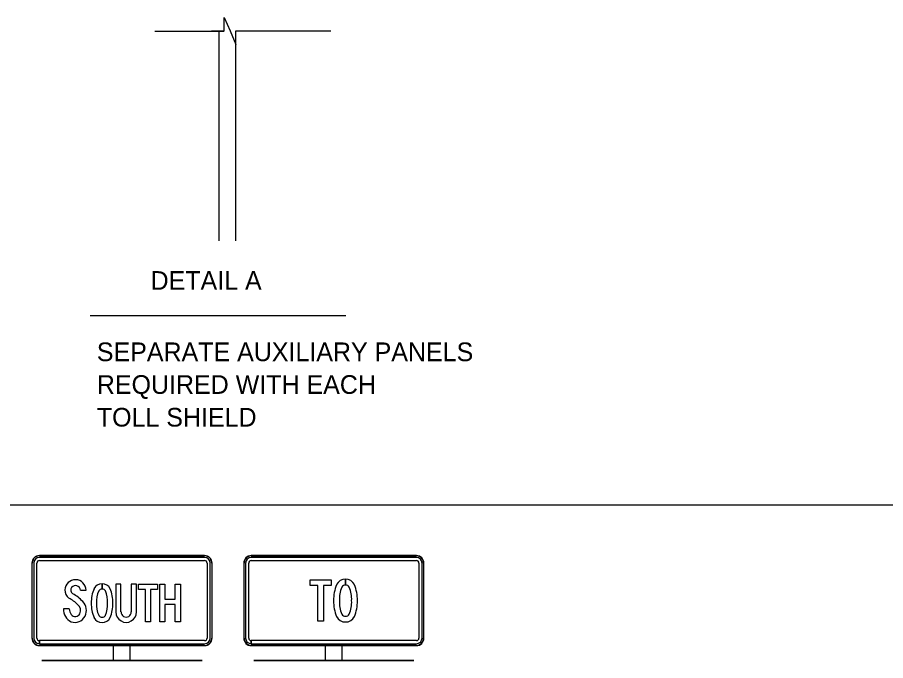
# Model space of a CAD drawing. Extents: x 530729 to 531367, y 1533250 to 1533664.
# Drawn here: x 530888.6 to 531018.7, y 1533454.4 to 1533550.8 of the extents above; entities that cross this region are included whole.
import ezdxf

# ---------------------------------------------------------------- set-up
doc = ezdxf.new("R2010")
doc.units = 0
for name, color, linetype in [('SheetBorder_dp', 7, 'Continuous'), ('SignPanel', 7, 'Continuous'), ('SignSupport', 7, 'Continuous'), ('TextLabel', 7, 'Continuous')]:
    doc.layers.add(name, color=color, linetype=linetype)

msp = doc.modelspace()

# ---------------------------------------------------------------- linework, layer by layer
at = {"layer": 'SheetBorder_dp'}
msp.add_line((530751.46, 1533477.75), (531367.46, 1533477.75), dxfattribs=at)
at = {"layer": 'SignPanel'}
for p, q in [((530918.87, 1533517.32), (530918.88, 1533548.76)), ((530921.38, 1533517.32), (530921.39, 1533548.78)), ((530916.69, 1533470.18), (530891.94, 1533470.18)), ((530916.69, 1533470.18), (530891.94, 1533470.18)), ((530891.94, 1533470.13), (530916.69, 1533470.13)), ((530916.69, 1533469.9), (530891.94, 1533469.9)), ((530891.94, 1533469.43), (530916.69, 1533469.43)), ((530903.06, 1533470.18), (530905.57, 1533470.18)), ((530948.43, 1533470.18), (530923.68, 1533470.18)), ((530948.43, 1533470.18), (530923.68, 1533470.18)), ((530923.68, 1533470.13), (530948.43, 1533470.13)), ((530948.43, 1533469.9), (530923.68, 1533469.9)), ((530923.68, 1533469.43), (530948.43, 1533469.43)), ((530934.8, 1533470.18), (530937.31, 1533470.18)), ((530890.81, 1533469.05), (530890.81, 1533457.8)), ((530890.81, 1533469.05), (530890.81, 1533457.8)), ((530890.86, 1533457.8), (530890.86, 1533469.05)), ((530891.09, 1533469.05), (530891.09, 1533457.8)), ((530891.56, 1533457.8), (530891.56, 1533469.05)), ((530917.06, 1533469.05), (530917.06, 1533457.8)), ((530917.53, 1533457.8), (530917.53, 1533469.05)), ((530917.77, 1533469.05), (530917.77, 1533457.8)), ((530917.81, 1533457.8), (530917.81, 1533469.05)), ((530917.81, 1533457.8), (530917.81, 1533469.05)), ((530922.56, 1533469.05), (530922.56, 1533457.8)), ((530922.56, 1533469.05), (530922.56, 1533457.8)), ((530922.6, 1533457.8), (530922.6, 1533469.05)), ((530922.84, 1533469.05), (530922.84, 1533457.8)), ((530923.31, 1533457.8), (530923.31, 1533469.05)), ((530948.81, 1533469.05), (530948.81, 1533457.8)), ((530949.28, 1533457.8), (530949.28, 1533469.05)), ((530949.51, 1533469.05), (530949.51, 1533457.8)), ((530949.56, 1533457.8), (530949.56, 1533469.05)), ((530949.56, 1533457.8), (530949.56, 1533469.05)), ((530901.34, 1533465.14), (530901.34, 1533465.93)), ((530901.34, 1533465.93), (530901.34, 1533465.14)), ((530901.34, 1533465.14), (530901.34, 1533465.93)), ((530901.34, 1533465.93), (530901.34, 1533465.14)), ((530903.4, 1533465.87), (530903.4, 1533461.72)), ((530903.4, 1533465.87), (530903.4, 1533461.72)), ((530903.4, 1533465.87), (530903.4, 1533461.72)), ((530937.81, 1533465.74), (530937.81, 1533466.62)), ((530937.81, 1533466.62), (530937.81, 1533465.74)), ((530937.81, 1533465.74), (530937.81, 1533466.62)), ((530937.81, 1533466.62), (530937.81, 1533465.74)), ((530898.09, 1533464.97), (530898.94, 1533464.97)), ((530898.09, 1533464.97), (530898.94, 1533464.97)), ((530898.09, 1533464.97), (530898.94, 1533464.97)), ((530896.43, 1533462.19), (530895.56, 1533462.19)), ((530896.43, 1533462.19), (530895.56, 1533462.19)), ((530896.43, 1533462.19), (530895.56, 1533462.19)), ((530891.94, 1533456.96), (530891.94, 1533457.43)), ((530916.69, 1533457.43), (530891.94, 1533457.43)), ((530891.94, 1533457.43), (530891.94, 1533456.96)), ((530891.94, 1533456.96), (530916.69, 1533456.96)), ((530891.94, 1533456.68), (530891.94, 1533456.73)), ((530916.69, 1533456.73), (530891.94, 1533456.73)), ((530891.94, 1533456.73), (530891.94, 1533456.68)), ((530891.94, 1533456.68), (530916.69, 1533456.68)), ((530891.94, 1533456.68), (530916.69, 1533456.68)), ((530903.05, 1533454.43), (530903.05, 1533456.73)), ((530905.56, 1533454.43), (530905.56, 1533456.73)), ((530923.68, 1533456.96), (530923.68, 1533457.43)), ((530923.68, 1533456.68), (530923.68, 1533456.73)), ((530948.43, 1533456.73), (530923.68, 1533456.73)), ((530923.68, 1533456.73), (530923.68, 1533456.68)), ((530923.68, 1533456.68), (530948.43, 1533456.68)), ((530923.68, 1533456.68), (530948.43, 1533456.68)), ((530948.43, 1533457.43), (530923.69, 1533457.43)), ((530923.69, 1533457.43), (530923.69, 1533456.96)), ((530923.69, 1533456.96), (530948.43, 1533456.96)), ((530934.8, 1533454.43), (530934.8, 1533456.68)), ((530937.31, 1533454.43), (530937.31, 1533456.68))]:
    msp.add_line(p, q, dxfattribs=at)
for points in [[(530904.17, 1533461.72), (530904.17, 1533465.87), (530903.4, 1533465.87)], [(530904.17, 1533461.72), (530904.17, 1533465.87), (530903.4, 1533465.87)], [(530904.17, 1533461.72), (530904.17, 1533465.87), (530903.4, 1533465.87)], [(530906.47, 1533461.72), (530906.47, 1533465.87), (530905.7, 1533465.87), (530905.7, 1533461.72)], [(530906.47, 1533461.72), (530906.47, 1533465.87), (530905.7, 1533465.87), (530905.7, 1533461.72)], [(530906.47, 1533461.72), (530906.47, 1533465.87), (530905.7, 1533465.87), (530905.7, 1533461.72)], [(530916.31, 1533454.43), (530892.31, 1533454.43)], [(530892.31, 1533454.43), (530916.31, 1533454.43)], [(530948.06, 1533454.43), (530924.06, 1533454.43)], [(530924.06, 1533454.43), (530948.06, 1533454.43)]]:
    msp.add_lwpolyline(points, dxfattribs=at)
for points in [[(530907.84, 1533465.08), (530906.81, 1533465.08), (530906.81, 1533465.87), (530909.64, 1533465.87), (530909.64, 1533465.08), (530908.61, 1533465.08), (530908.61, 1533460.24), (530907.84, 1533460.24)], [(530907.84, 1533465.08), (530906.81, 1533465.08), (530906.81, 1533465.87), (530909.64, 1533465.87), (530909.64, 1533465.08), (530908.61, 1533465.08), (530908.61, 1533460.24), (530907.84, 1533460.24)], [(530907.84, 1533465.08), (530906.81, 1533465.08), (530906.81, 1533465.87), (530909.64, 1533465.87), (530909.64, 1533465.08), (530908.61, 1533465.08), (530908.61, 1533460.24), (530907.84, 1533460.24)], [(530909.98, 1533465.87), (530910.76, 1533465.87), (530910.76, 1533463.62), (530912.28, 1533463.62), (530912.28, 1533465.87), (530913.06, 1533465.87), (530913.06, 1533460.24), (530912.28, 1533460.24), (530912.28, 1533462.83), (530910.76, 1533462.83), (530910.76, 1533460.24), (530909.98, 1533460.24)], [(530909.98, 1533465.87), (530910.76, 1533465.87), (530910.76, 1533463.62), (530912.28, 1533463.62), (530912.28, 1533465.87), (530913.06, 1533465.87), (530913.06, 1533460.24), (530912.28, 1533460.24), (530912.28, 1533462.83), (530910.76, 1533462.83), (530910.76, 1533460.24), (530909.98, 1533460.24)], [(530909.98, 1533465.87), (530910.76, 1533465.87), (530910.76, 1533463.62), (530912.28, 1533463.62), (530912.28, 1533465.87), (530913.06, 1533465.87), (530913.06, 1533460.24), (530912.28, 1533460.24), (530912.28, 1533462.83), (530910.76, 1533462.83), (530910.76, 1533460.24), (530909.98, 1533460.24)], [(530933.65, 1533465.67), (530932.52, 1533465.67), (530932.52, 1533466.54), (530935.64, 1533466.54), (530935.64, 1533465.67), (530934.51, 1533465.67), (530934.51, 1533460.32), (530933.65, 1533460.32)], [(530933.65, 1533465.67), (530932.52, 1533465.67), (530932.52, 1533466.54), (530935.64, 1533466.54), (530935.64, 1533465.67), (530934.51, 1533465.67), (530934.51, 1533460.32), (530933.65, 1533460.32)], [(530933.65, 1533465.67), (530932.52, 1533465.67), (530932.52, 1533466.54), (530935.64, 1533466.54), (530935.64, 1533465.67), (530934.51, 1533465.67), (530934.51, 1533460.32), (530933.65, 1533460.32)]]:
    msp.add_lwpolyline(points, close=True, dxfattribs=at)
for centre, radius, start, end in [((530891.94, 1533469.05), 1.12, 90, 180), ((530891.94, 1533469.05), 1.12, 90, 180), ((530891.94, 1533469.05), 1.08, 90, 180), ((530891.94, 1533469.05), 0.844, 90, 180), ((530891.94, 1533469.05), 0.375, 90, 180), ((530916.69, 1533469.05), 1.12, 0, 90), ((530916.69, 1533469.05), 1.12, 0, 90), ((530916.69, 1533469.05), 1.08, 0, 90), ((530916.69, 1533469.05), 0.844, 0, 90), ((530916.69, 1533469.05), 0.375, 0, 90), ((530923.68, 1533469.05), 1.12, 90, 180), ((530923.68, 1533469.05), 1.12, 90, 180), ((530923.68, 1533469.05), 1.08, 90, 180), ((530923.68, 1533469.05), 0.844, 90, 180), ((530923.68, 1533469.05), 0.375, 90, 180), ((530948.43, 1533469.05), 1.12, 0, 90), ((530948.43, 1533469.05), 1.12, 0, 90), ((530948.43, 1533469.05), 1.08, 0, 90), ((530948.43, 1533469.05), 0.844, 0, 90), ((530948.43, 1533469.05), 0.375, 0, 90), ((530891.94, 1533457.8), 1.12, 180, 270), ((530891.94, 1533457.8), 1.12, 180, 270), ((530891.94, 1533457.8), 1.08, 180, 270), ((530891.94, 1533457.8), 0.844, 180, 270), ((530891.94, 1533457.8), 0.375, 180, 270), ((530916.69, 1533457.8), 1.12, 270, 0), ((530916.69, 1533457.8), 0.844, 270, 0), ((530916.69, 1533457.8), 0.375, 270, 0), ((530916.69, 1533457.8), 1.12, 270, 0), ((530916.69, 1533457.8), 1.08, 270, 0), ((530923.68, 1533457.8), 1.12, 180, 270), ((530923.68, 1533457.8), 1.12, 180, 270), ((530923.68, 1533457.8), 1.08, 180, 270), ((530923.68, 1533457.8), 0.844, 180, 270), ((530923.68, 1533457.8), 0.375, 180, 270), ((530948.43, 1533457.8), 1.12, 270, 0), ((530948.43, 1533457.8), 0.844, 270, 0), ((530948.43, 1533457.8), 0.375, 270, 0), ((530948.43, 1533457.8), 1.12, 270, 0), ((530948.43, 1533457.8), 1.08, 270, 0)]:
    msp.add_arc(centre, radius, start, end, dxfattribs=at)
for centre, major_axis, start_param, end_param in [((530897.35, 1533464.93), (0, 1.62), 4.736267, 7.790596), ((530897.35, 1533464.93), (0, 1.62), 4.736267, 7.790596), ((530897.35, 1533464.93), (0, 1.62), 4.736267, 7.790596), ((530897.25, 1533465.01), (0, 0.626), 0.87378, 2.656959), ((530897.25, 1533465.01), (0, 0.626), 0.87378, 2.656959), ((530897.25, 1533465.01), (0, 0.626), 0.87378, 2.656959), ((530897.34, 1533464.91), (0, 0.76), 4.786904, 7.140738), ((530897.34, 1533464.91), (0, 0.76), 4.786904, 7.140738), ((530897.34, 1533464.91), (0, 0.76), 4.786904, 7.140738), ((530901.29, 1533464.61), (0, 1.33), 6.248265, 7.383959), ((530901.29, 1533464.61), (0, 1.33), 6.248265, 7.383959), ((530901.29, 1533464.61), (0, 1.33), 6.248265, 7.383959), ((530901.38, 1533464.61), (0, 1.33), 5.182411, 6.318105), ((530901.38, 1533464.61), (0, 1.33), 5.182411, 6.317893), ((530901.38, 1533464.61), (0, 1.33), 5.182411, 6.317893), ((530941.83, 1533463.53), (0, 5.9), 1.174158, 1.59042), ((530941.83, 1533463.53), (0, 5.9), 1.174158, 1.59042), ((530941.83, 1533463.53), (0, 5.9), 1.174158, 1.59042), ((530937.76, 1533465.15), (0, 1.47), 6.248265, 7.383959), ((530937.76, 1533465.15), (0, 1.47), 6.248265, 7.383959), ((530937.76, 1533465.15), (0, 1.47), 6.248265, 7.383959), ((530941.45, 1533463.63), (0, 4.64), 1.169623, 1.616135), ((530941.45, 1533463.63), (0, 4.64), 1.169623, 1.616135), ((530941.45, 1533463.63), (0, 4.64), 1.169623, 1.616135), ((530937.77, 1533465.11), (0, 0.627), 6.22959, 7.30809), ((530937.77, 1533465.11), (0, 0.627), 6.22959, 7.30809), ((530937.77, 1533465.11), (0, 0.627), 6.22959, 7.30809), ((530937.86, 1533465.15), (0, 1.47), 5.182411, 6.318105), ((530937.86, 1533465.15), (0, 1.47), 5.182411, 6.317893), ((530937.86, 1533465.15), (0, 1.47), 5.182411, 6.317893), ((530937.84, 1533465.11), (0, 0.627), 5.258281, 6.33678), ((530937.84, 1533465.11), (0, 0.627), 5.258281, 6.336283), ((530937.84, 1533465.11), (0, 0.627), 5.258281, 6.336283), ((530934.16, 1533463.63), (0, 4.64), 4.667051, 5.113562), ((530934.16, 1533463.63), (0, 4.64), 4.667051, 5.113562), ((530934.16, 1533463.63), (0, 4.64), 4.667051, 5.113562), ((530933.78, 1533463.53), (0, 5.9), 4.692766, 5.109028), ((530933.78, 1533463.53), (0, 5.9), 4.692766, 5.109028), ((530933.78, 1533463.53), (0, 5.9), 4.692766, 5.109028), ((530897.19, 1533464.98), (0, 1.45), 1.534831, 2.511766), ((530897.19, 1533464.98), (0, 1.45), 1.534831, 2.511766), ((530897.19, 1533464.98), (0, 1.45), 1.534831, 2.511766), ((530894.13, 1533459.21), (0, 5.97), 5.462886, 5.782242), ((530894.13, 1533459.21), (0, 5.97), 5.462886, 5.782242), ((530894.13, 1533459.21), (0, 5.97), 5.462886, 5.782242), ((530904.97, 1533463.15), (0, 5.33), 1.174158, 1.59042), ((530904.97, 1533463.15), (0, 5.33), 1.174158, 1.59042), ((530904.97, 1533463.15), (0, 5.33), 1.174158, 1.59042), ((530904.63, 1533463.23), (0, 4.19), 1.169623, 1.616135), ((530904.63, 1533463.23), (0, 4.19), 1.169623, 1.616135), ((530904.63, 1533463.23), (0, 4.19), 1.169623, 1.616135), ((530901.31, 1533464.58), (0, 0.567), 6.22959, 7.30809), ((530901.31, 1533464.58), (0, 0.567), 6.22959, 7.30809), ((530901.31, 1533464.58), (0, 0.567), 6.22959, 7.30809), ((530901.37, 1533464.58), (0, 0.567), 5.258281, 6.33678), ((530901.37, 1533464.58), (0, 0.567), 5.258281, 6.336283), ((530901.37, 1533464.58), (0, 0.567), 5.258281, 6.336283), ((530898.04, 1533463.23), (0, 4.19), 4.667051, 5.113562), ((530898.04, 1533463.23), (0, 4.19), 4.667051, 5.113562), ((530898.04, 1533463.23), (0, 4.19), 4.667051, 5.113562), ((530897.7, 1533463.15), (0, 5.33), 4.692766, 5.109028), ((530897.7, 1533463.15), (0, 5.33), 4.692766, 5.109028), ((530897.7, 1533463.15), (0, 5.33), 4.692766, 5.109028), ((530893.39, 1533458.26), (0, 6.31), 5.515137, 5.786988), ((530893.39, 1533458.26), (0, 6.31), 5.515137, 5.786988), ((530893.39, 1533458.26), (0, 6.31), 5.515137, 5.786988), ((530897.06, 1533461.94), (0, 1.08), 4.254409, 5.632398), ((530897.06, 1533461.94), (0, 1.08), 4.254409, 5.632398), ((530897.06, 1533461.94), (0, 1.08), 4.254409, 5.632398), ((530897.08, 1533461.94), (0, 1.93), 4.260987, 5.485755), ((530897.08, 1533461.94), (0, 1.93), 4.260987, 5.485755), ((530897.08, 1533461.94), (0, 1.93), 4.260987, 5.485755), ((530904.97, 1533462.94), (0, 5.33), 1.551173, 1.967435), ((530904.97, 1533462.94), (0, 5.33), 1.551173, 1.967435), ((530904.97, 1533462.94), (0, 5.33), 1.551173, 1.967435), ((530904.63, 1533462.86), (0, 4.19), 1.525458, 1.97197), ((530904.63, 1533462.86), (0, 4.19), 1.525458, 1.97197), ((530904.63, 1533462.86), (0, 4.19), 1.525458, 1.97197), ((530898.04, 1533462.86), (0, 4.19), 4.311216, 4.757727), ((530898.04, 1533462.86), (0, 4.19), 4.311216, 4.757727), ((530898.04, 1533462.86), (0, 4.19), 4.311216, 4.757727), ((530897.7, 1533462.94), (0, 5.33), 4.31575, 4.732012), ((530897.7, 1533462.94), (0, 5.33), 4.31575, 4.732012), ((530897.7, 1533462.94), (0, 5.33), 4.31575, 4.732012), ((530941.83, 1533463.3), (0, 5.9), 1.551173, 1.967435), ((530941.83, 1533463.3), (0, 5.9), 1.551173, 1.967435), ((530941.83, 1533463.3), (0, 5.9), 1.551173, 1.967435), ((530941.45, 1533463.21), (0, 4.64), 1.525458, 1.97197), ((530941.45, 1533463.21), (0, 4.64), 1.525458, 1.97197), ((530941.45, 1533463.21), (0, 4.64), 1.525458, 1.97197), ((530934.16, 1533463.21), (0, 4.64), 4.311216, 4.757727), ((530934.16, 1533463.21), (0, 4.64), 4.311216, 4.757727), ((530934.16, 1533463.21), (0, 4.64), 4.311216, 4.757727), ((530933.78, 1533463.3), (0, 5.9), 4.31575, 4.732012), ((530933.78, 1533463.3), (0, 5.9), 4.31575, 4.732012), ((530933.78, 1533463.3), (0, 5.9), 4.31575, 4.732012), ((530897.56, 1533462.1), (0, 2.03), 1.526364, 2.701682), ((530897.56, 1533462.1), (0, 2.03), 1.526364, 2.701682), ((530897.56, 1533462.1), (0, 2.03), 1.526364, 2.701682), ((530897.65, 1533462.14), (0, 1.24), 1.524757, 2.28214), ((530897.65, 1533462.14), (0, 1.24), 1.524757, 2.28214), ((530897.65, 1533462.14), (0, 1.24), 1.524757, 2.28214), ((530897.32, 1533461.83), (0, 0.79), 2.261787, 4.23006), ((530897.32, 1533461.83), (0, 0.79), 2.261787, 4.23006), ((530897.32, 1533461.83), (0, 0.79), 2.261787, 4.23006), ((530904.94, 1533461.72), (0, 1.56), 1.570796, 4.712389), ((530904.94, 1533461.72), (0, 1.56), 1.570796, 4.712389), ((530904.94, 1533461.72), (0, 1.56), 1.570796, 4.712389), ((530904.94, 1533461.72), (0, 0.773), 1.570796, 4.712389), ((530904.94, 1533461.72), (0, 0.773), 1.570796, 4.712389), ((530904.94, 1533461.72), (0, 0.773), 1.570796, 4.712389), ((530897.29, 1533461.85), (0, 1.69), 2.786047, 4.251692), ((530897.29, 1533461.85), (0, 1.69), 2.786047, 4.251692), ((530897.29, 1533461.85), (0, 1.69), 2.786047, 4.251692), ((530901.29, 1533461.48), (0, 1.33), 2.040819, 3.176513), ((530901.29, 1533461.48), (0, 1.33), 2.040819, 3.176513), ((530901.29, 1533461.48), (0, 1.33), 2.040819, 3.176513), ((530901.31, 1533461.51), (0, 0.567), 2.116688, 3.195188), ((530901.31, 1533461.51), (0, 0.567), 2.116688, 3.195188), ((530901.31, 1533461.51), (0, 0.567), 2.116688, 3.195188), ((530901.37, 1533461.51), (0, 0.567), 3.087997, 4.166497), ((530901.37, 1533461.51), (0, 0.567), 3.087997, 4.166497), ((530901.37, 1533461.51), (0, 0.567), 3.087997, 4.166497), ((530901.38, 1533461.48), (0, 1.33), 3.106673, 4.242367), ((530901.38, 1533461.48), (0, 1.33), 3.106673, 4.242367), ((530901.38, 1533461.48), (0, 1.33), 3.106673, 4.242367), ((530937.76, 1533461.69), (0, 1.47), 2.040819, 3.176513), ((530937.76, 1533461.69), (0, 1.47), 2.040819, 3.176513), ((530937.76, 1533461.69), (0, 1.47), 2.040819, 3.176513), ((530937.77, 1533461.72), (0, 0.627), 2.116688, 3.195188), ((530937.77, 1533461.72), (0, 0.627), 2.116688, 3.195188), ((530937.77, 1533461.72), (0, 0.627), 2.116688, 3.195188), ((530937.84, 1533461.72), (0, 0.627), 3.087997, 4.166497), ((530937.84, 1533461.72), (0, 0.627), 3.087997, 4.166497), ((530937.84, 1533461.72), (0, 0.627), 3.087997, 4.166497), ((530937.86, 1533461.69), (0, 1.47), 3.106673, 4.242367), ((530937.86, 1533461.69), (0, 1.47), 3.106673, 4.242367), ((530937.86, 1533461.69), (0, 1.47), 3.106673, 4.242367)]:
    msp.add_ellipse(centre, major_axis=major_axis, ratio=0.985, start_param=start_param, end_param=end_param, dxfattribs=at)
at = {"layer": 'SignSupport'}
for p, q in [((530909.23, 1533548.76), (530919.61, 1533548.76)), ((530923.06, 1533548.78), (530935.59, 1533548.78))]:
    msp.add_line(p, q, dxfattribs=at)
msp.add_lwpolyline([(530917.71, 1533548.78), (530919.61, 1533548.78), (530919.61, 1533550.81), (530920.5, 1533548.78), (530921.39, 1533546.74), (530921.39, 1533548.78), (530923.29, 1533548.78)], dxfattribs=at)
at = {"layer": 'TextLabel'}
msp.add_line((530899.56, 1533506.15), (530937.83, 1533506.15), dxfattribs=at)

# ---------------------------------------------------------------- texts
for s, p in [('DETAIL A', (530908.6, 1533509.99)), ('SEPARATE AUXILIARY PANELS', (530900.55, 1533499.3)), ('REQUIRED WITH EACH', (530900.55, 1533494.4)), ('TOLL SHIELD', (530900.55, 1533489.5))]:
    msp.add_text(s, height=2.8, dxfattribs=at).set_placement(p)

doc.saveas('drawing.dxf')
